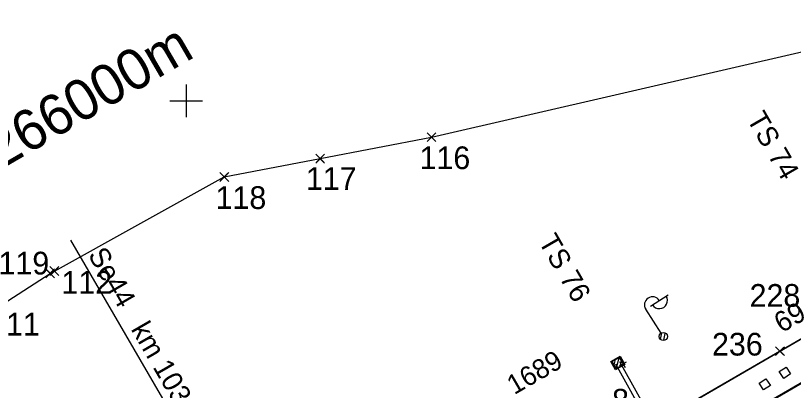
# Model space of a CAD drawing. Extents: x -566182 to -565305, y -1203073 to -1202401.
# Drawn here: x -565821 to -565725.2, y -1202735.7 to -1202689.5 of the extents above; entities that cross this region are included whole.
import ezdxf

# ---------------------------------------------------------------- set-up
doc = ezdxf.new("R2010")
doc.units = 0
for name, color, linetype in [('CD', 7, 'Continuous'), ('LÁTAL_SVRŠEK', 7, 'Continuous'), ('Vrstva 10', 7, 'Continuous'), ('Vrstva 12', 7, 'Continuous'), ('Vrstva 13', 7, 'Continuous'), ('Vrstva 25', 7, 'Continuous'), ('Vrstva 39', 7, 'Continuous'), ('Vrstva 40', 7, 'Continuous'), ('Vrstva 5', 7, 'Continuous'), ('Vrstva 6', 7, 'Continuous'), ('Vrstva 60', 7, 'Continuous'), ('Vrstva 62', 7, 'Continuous'), ('Vrstva 63', 7, 'Continuous'), ('Vrstva 9', 7, 'Continuous')]:
    doc.layers.add(name, color=color, linetype=linetype)

# ---------------------------------------------------------------- blocks, each defined once
blk = doc.blocks.new('EOV')
at = {"layer": 'Vrstva 62'}
blk.add_lwpolyline([(-5, 5), (5, 5), (5, -5), (-5, -5)], close=True, dxfattribs=at)
blk = doc.blocks.new('C691')
at = {"layer": 'Vrstva 12'}
for p, q in [((-5, 0), (5, 0)), ((0, 5), (0, -5))]:
    blk.add_line(p, q, dxfattribs=at)
blk = doc.blocks.new('C669')
at = {"layer": 'Vrstva 6'}
for p, q in [((0, 5), (0, 40.01)), ((7, 40.01), (33, 40.01)), ((-5, -1), (1, 5)), ((-2, -4), (4.01, 2))]:
    blk.add_line(p, q, dxfattribs=at)
blk.add_circle((0, 0), 5, dxfattribs=at)
blk.add_circle((0, 0), 5, dxfattribs=at)
for centre, start, end in [((10, 40.01), 0.00006, 180.00006), ((20, 39.89), 179.29748, 0.70263)]:
    blk.add_arc(centre, 10, start, end, dxfattribs=at)
blk = doc.blocks.new('C661_2')
at = {"layer": 'Vrstva 12'}
for p, q in [((-5.01, 0.33), (-0.33, 4.99)), ((-5, -4.96), (4.96, 5)), ((0.27, -5), (5, -0.27))]:
    blk.add_line(p, q, dxfattribs=at)
blk.add_lwpolyline([(-5, 5), (5, 5), (5, -5), (-5, -5)], close=True, dxfattribs=at)
blk.add_lwpolyline([(-5, 5), (5, 5), (5, -5), (-5, -5), (-5, 5)], dxfattribs=at)
blk = doc.blocks.new('EOV_1')
at = {"layer": 'Vrstva 40'}
blk.add_lwpolyline([(-5, 5), (5, 5), (5, -5), (-5, -5)], close=True, dxfattribs=at)

msp = doc.modelspace()

# ---------------------------------------------------------------- linework, layer by layer
at = {"layer": 'CD'}
for p, q in [((-565769.79, -1202704.47), (-565716.98, -1202692.29)), ((-565783.5, -1202707.11), (-565769.79, -1202704.47)), ((-565795.32, -1202709.38), (-565783.5, -1202707.11)), ((-565816.24, -1202720.98), (-565795.32, -1202709.38)), ((-565824.28, -1202726.13), (-565816.76, -1202721.27)), ((-565816.76, -1202721.27), (-565816.24, -1202720.98))]:
    msp.add_line(p, q, dxfattribs=at)
at = {"layer": 'LÁTAL_SVRŠEK'}
for p, q in [((-565750.835, -1202744.772), (-565723.905, -1202729.137)), ((-565739.205, -1202743.507), (-565721.522, -1202733.24))]:
    msp.add_line(p, q, dxfattribs=at)
at = {"layer": 'Vrstva 10'}
for p, q in [((-565747.704, -1202732.128), (-565746.553, -1202731.469)), ((-565747.137, -1202733.173), (-565747.704, -1202732.128)), ((-565746.553, -1202731.469), (-565745.979, -1202732.497)), ((-565745.979, -1202732.497), (-565747.137, -1202733.173))]:
    msp.add_line(p, q, dxfattribs=at)
at = {"layer": 'Vrstva 12'}
for points in [[(-565734.324, -1202754.231), (-565746.579, -1202732.165)], [(-565734.848, -1202754.523), (-565747.103, -1202732.457)]]:
    msp.add_lwpolyline(points, dxfattribs=at)
at = {"layer": 'Vrstva 5'}
for p, q in [((-565800, -1202698), (-565800, -1202702)), ((-565802, -1202700), (-565798, -1202700))]:
    msp.add_line(p, q, dxfattribs=at)
at = {"layer": 'Vrstva 6'}
for points in [[(-565772.18, -1202757.12), (-565716.36, -1202724.73), (-565690.38, -1202709.64), (-565661.87, -1202693.06), (-565648.68, -1202685.41), (-565628.31, -1202673.57)], [(-565721.54, -1202733.21), (-565758.57, -1202754.71)]]:
    msp.add_lwpolyline(points, dxfattribs=at)
for centre, radius, start, end in [((-565537.538, -1202971.947), 298.852, 126.50209, 129.52225), ((-565542.201, -1203010.873), 325.318, 121.31641, 124.53128)]:
    msp.add_arc(centre, radius, start, end, dxfattribs=at)
at = {"layer": 'Vrstva 60'}
for p, q in [((-565769.34, -1202704.92), (-565770.34, -1202703.92)), ((-565769.34, -1202704.02), (-565770.34, -1202705.02)), ((-565770.24, -1202704.92), (-565769.24, -1202703.92)), ((-565770.24, -1202704.02), (-565769.24, -1202705.02)), ((-565769.79, -1202704.47), (-565769.79, -1202704.47)), ((-565783.05, -1202707.56), (-565784.05, -1202706.56)), ((-565783.05, -1202706.66), (-565784.05, -1202707.66)), ((-565783.95, -1202707.56), (-565782.95, -1202706.56)), ((-565783.95, -1202706.66), (-565782.95, -1202707.66)), ((-565783.5, -1202707.11), (-565783.5, -1202707.11)), ((-565794.87, -1202709.83), (-565795.87, -1202708.83)), ((-565794.87, -1202708.93), (-565795.87, -1202709.93)), ((-565795.77, -1202709.83), (-565794.77, -1202708.83)), ((-565795.77, -1202708.93), (-565794.77, -1202709.93)), ((-565795.32, -1202709.38), (-565795.32, -1202709.38)), ((-565814.264, -1202717.163), (-565782.185, -1202772.276)), ((-565816.31, -1202721.72), (-565817.31, -1202720.72)), ((-565817.21, -1202721.72), (-565816.21, -1202720.72)), ((-565815.79, -1202721.43), (-565816.79, -1202720.43)), ((-565815.79, -1202720.53), (-565816.79, -1202721.53)), ((-565816.69, -1202721.43), (-565815.69, -1202720.43)), ((-565816.69, -1202720.53), (-565815.69, -1202721.53)), ((-565816.31, -1202720.82), (-565817.31, -1202721.82)), ((-565817.21, -1202720.82), (-565816.21, -1202721.82)), ((-565816.76, -1202721.27), (-565816.76, -1202721.27)), ((-565816.24, -1202720.98), (-565816.24, -1202720.98)), ((-565726.418, -1202731.307), (-565727.418, -1202730.307)), ((-565727.318, -1202731.307), (-565726.318, -1202730.307)), ((-565726.418, -1202730.407), (-565727.418, -1202731.407)), ((-565727.318, -1202730.407), (-565726.318, -1202731.407)), ((-565726.868, -1202730.857), (-565726.868, -1202730.857))]:
    msp.add_line(p, q, dxfattribs=at)

# ---------------------------------------------------------------- block references
at = {"layer": 'Vrstva 12'}
for name, p, xscale, yscale, rotation in [('C661_2', (-565746.841, -1202732.311), 0.10000022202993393, 0.10000022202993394, 30.276660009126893), ('C691', (-565746.194, -1202732.43), 0.09999990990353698, 0.09999990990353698, 30.000029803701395)]:
    msp.add_blockref(name, p, dxfattribs=dict(at, xscale=xscale, yscale=yscale, rotation=rotation))
at = {"layer": 'Vrstva 40', "xscale": 0.10000003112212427, "yscale": 0.10000003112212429, "rotation": 32.99994277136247}
for p in [(-565726.264, -1202733.524), (-565728.739, -1202734.948)]:
    msp.add_blockref('EOV_1', p, dxfattribs=at)
at = {"layer": 'Vrstva 6', "xscale": 0.10000003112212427, "yscale": 0.10000003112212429, "rotation": 32.99994277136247}
msp.add_blockref('C669', (-565741.229, -1202729.055), dxfattribs=at)
at = {"layer": 'Vrstva 62', "xscale": 0.10000003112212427, "yscale": 0.10000003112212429, "rotation": 32.99994277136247}
for p in [(-565726.264, -1202733.524), (-565728.739, -1202734.948)]:
    msp.add_blockref('EOV', p, dxfattribs=at)

# ---------------------------------------------------------------- texts
at = {"layer": 'Vrstva 13'}
for s, p in [('TS 74', (-565731.012, -1202702.236)), ('TS 76', (-565756.672, -1202717.327))]:
    msp.add_text(s, height=2.5, rotation=300, dxfattribs=at).set_placement(p)
at = {"layer": 'Vrstva 25'}
msp.add_text('Se44   km 103.078', height=2.5, rotation=299.98733, dxfattribs=at).set_placement((-565812.16, -1202718.965))
at = {"layer": 'Vrstva 39'}
msp.add_text('r=266000m', height=5, rotation=30.149, dxfattribs=at).set_placement((-565828.198, -1202711.605))
at = {"layer": 'Vrstva 60'}
for s, p in [('116', (-565771.263, -1202708.417)), ('117', (-565785.26, -1202710.975)), ('118', (-565796.384, -1202713.327)), ('119', (-565823.119, -1202721.403)), ('112', (-565815.375, -1202723.78)), ('228', (-565730.611, -1202725.39)), ('111', (-565824.28, -1202728.93)), ('236', (-565735.239, -1202731.401)), ('8', (-565747.548, -1202738.314))]:
    msp.add_text(s, height=2.8, dxfattribs=at).set_placement(p)
at = {"layer": 'Vrstva 63'}
msp.add_text('1689', height=2.4, rotation=30.16402, dxfattribs=at).set_placement((-565759.596, -1202736.288))
at = {"layer": 'Vrstva 9'}
msp.add_text('69', height=2.5, rotation=30.14486, dxfattribs=at).set_placement((-565726.659, -1202728.669))

doc.saveas('drawing.dxf')
